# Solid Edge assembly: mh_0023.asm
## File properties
Title: grip_l_unit
Author: edge
Template: normal.asm
Last saved by: edge
Revision: 32
Application: Solid Edge
文書内容のタイプ: 1
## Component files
mh_0025.par
mh_0024.par
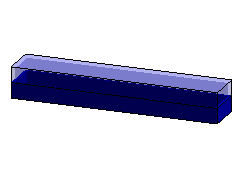
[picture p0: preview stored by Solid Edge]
